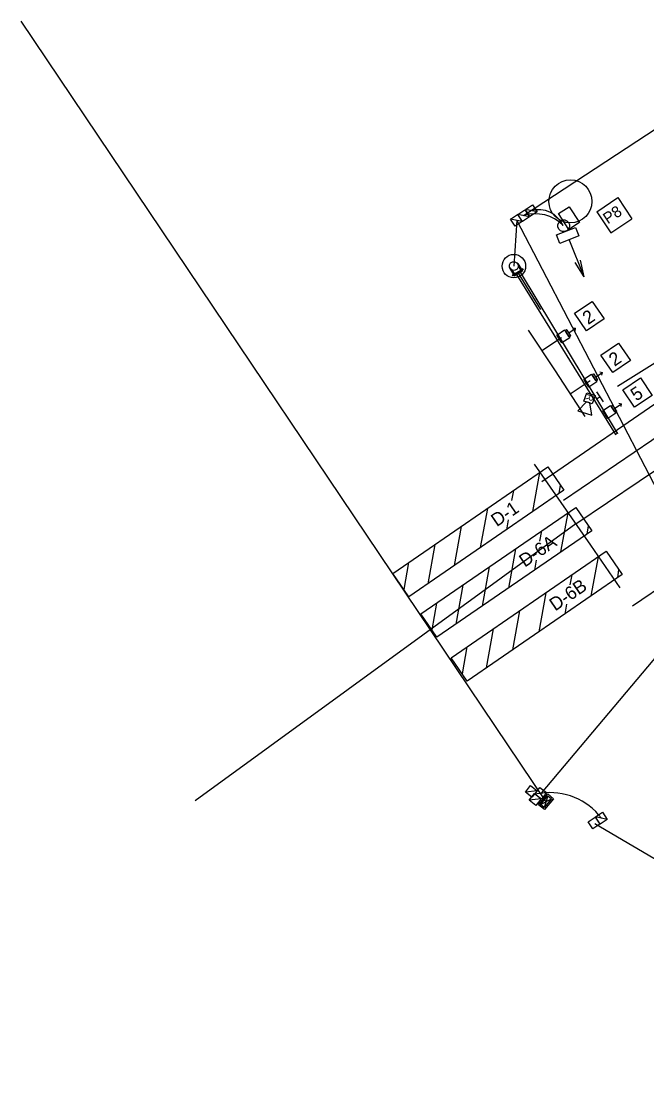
# Model space of a CAD drawing. Extents: x 509004 to 509991, y 882089 to 882397.
# Drawn here: x 509003.6 to 509136.6, y 882120.7 to 882344.8 of the extents above; entities that cross this region are included whole.
import ezdxf

# ---------------------------------------------------------------- set-up
doc = ezdxf.new("R2010")
doc.units = 0
for name, color, linetype in [('CLConst_dp', 7, 'Continuous'), ('ConstLines', 7, 'Continuous'), ('Default', 7, 'Continuous'), ('TextAlgnCardinalPnt', 7, 'Continuous'), ('TextAlgnCurveData', 7, 'Continuous'), ('TextAlgnStation100', 7, 'Continuous'), ('TextAlgnStation1000', 7, 'Continuous'), ('TextAlgnStation500', 7, 'Continuous'), ('TextAlgnStation5000', 7, 'Continuous'), ('TextAlgnTangent', 7, 'Continuous'), ('TextAlgnTicks1000', 7, 'Continuous'), ('TextAlgnTicks500', 7, 'Continuous'), ('TextAlgnTicks5000', 7, 'Continuous')]:
    doc.layers.add(name, color=color, linetype=linetype)

msp = doc.modelspace()

# ---------------------------------------------------------------- linework, layer by layer
at = {"layer": 'CLConst_dp'}
for p, q in [((509107.51, 882292.21), (509107.56, 882292.24)), ((509107.51, 882292.21), (509108.28, 882290.94)), ((509107.56, 882292.24), (509108.33, 882290.98)), ((509107.94, 882291.89), (509108.5, 882290.98)), ((509110.35, 882292), (509108.07, 882290.61)), ((509108.32, 882290.77), (509110.1, 882291.85)), ((509109.82, 882291.79), (509108.5, 882290.98)), ((509109.18, 882293.23), (509109.13, 882293.2)), ((509109.13, 882293.2), (509109.9, 882291.93)), ((509109.18, 882293.23), (509109.96, 882291.97)), ((509109.27, 882292.7), (509109.82, 882291.79)), ((509110.26, 882292.15), (509109.78, 882291.86)), ((509110.1, 882291.85), (509110.18, 882291.71)), ((509110.26, 882292.15), (509110.35, 882292)), ((509108.46, 882291.05), (509107.98, 882290.76)), ((509107.98, 882290.76), (509108.07, 882290.61)), ((509108.32, 882290.77), (509108.41, 882290.62)), ((509108.41, 882290.62), (509110.18, 882291.71)), ((509108.9, 882290.93), (509129.95, 882256.91)), ((509109.69, 882291.41), (509130.34, 882257.15)), ((509130.44, 882257.21), (509129.84, 882256.85))]:
    msp.add_line(p, q, dxfattribs=at)
msp.add_lwpolyline([(509109.04, 882292.06), (509108.62, 882291.81), (509108.12, 882291.79), (509107.69, 882292.03), (509107.43, 882292.45), (509107.42, 882292.94), (509107.66, 882293.37), (509108.08, 882293.63), (509108.57, 882293.64), (509109, 882293.41), (509109.26, 882292.99), (509109.27, 882292.49)], close=True, dxfattribs=at)
msp.add_circle((509108.35, 882292.7), 2.5, dxfattribs=at)
at = {"layer": 'ConstLines'}
for p, q in [((509115.19, 882178.82), (509003.6, 882344.8)), ((509238.53, 882335.06), (509130.35, 882267.1)), ((509114.28, 882246.89), (509215.66, 882316.8)), ((509121.5, 882237.9), (509226.04, 882308.24)), ((509114.27, 882274.75), (509118.51, 882277.53)), ((509120.29, 882265.57), (509124.54, 882268.35)), ((509118.93, 882242.94), (509141.44, 882258.22)), ((509121.5, 882237.9), (509040.64, 882179.01))]:
    msp.add_line(p, q, dxfattribs=at)
for points in [[(509111.42, 882279.1), (509117.13, 882270.4), (509123.46, 882260.74)], [(509112.68, 882250.62), (509118.37, 882242.43), (509124.63, 882233.36), (509130.88, 882224.29)]]:
    msp.add_lwpolyline(points, dxfattribs=at)
msp.add_circle((509120.38, 882306.46), 4.58, dxfattribs=at)
at = {"layer": 'Default'}
msp.add_line((509133.54, 882220.5), (509164.96, 882241.77), dxfattribs=at)
at = {"layer": 'TextAlgnCardinalPnt'}
for p, q in [((509150.12, 882223.33), (509108.95, 882302.45)), ((509114.21, 882180.66), (509150.12, 882223.33))]:
    msp.add_line(p, q, dxfattribs=at)
at = {"layer": 'TextAlgnCurveData'}
for p, q in [((509110.42, 882303.44), (509138.84, 882322.08)), ((509108.95, 882302.45), (509108.35, 882292.72))]:
    msp.add_line(p, q, dxfattribs=at)
for centre, radius, start, end in [((509112.91, 882295.6), 8.23, 43.9393, 107.6121), ((509113.56, 882298.91), 5.79, 24.4306, 105.2087), ((509116.08, 882167.13), 13.62, 36.983, 98.5568)]:
    msp.add_arc(centre, radius, start, end, dxfattribs=at)
at = {"layer": 'TextAlgnStation100'}
for p, q in [((509110.8, 882304.76), (509112.3, 882305.74)), ((509112.3, 882305.74), (509113.28, 882304.24)), ((509107.64, 882302.69), (509109.14, 882303.67)), ((509109.14, 882303.67), (509110.12, 882302.17)), ((509109.18, 882303.7), (509110.68, 882304.68)), ((509110.16, 882302.2), (509109.18, 882303.7)), ((509111.66, 882303.18), (509109.18, 882303.7)), ((509111.66, 882303.18), (509110.16, 882302.2)), ((509110.68, 882304.68), (509111.66, 882303.18)), ((509111.78, 882303.26), (509110.8, 882304.76)), ((509113.28, 882304.24), (509110.8, 882304.76)), ((509113.28, 882304.24), (509111.78, 882303.26)), ((509108.62, 882301.19), (509107.64, 882302.69)), ((509110.12, 882302.17), (509107.64, 882302.69)), ((509110.12, 882302.17), (509108.62, 882301.19)), ((509110.79, 882180.86), (509111.89, 882182.27)), ((509111.89, 882182.27), (509113.3, 882181.17)), ((509113.3, 882181.17), (509110.79, 882180.86)), ((509112.2, 882179.76), (509110.79, 882180.86)), ((509111.61, 882179.13), (509112.71, 882180.54)), ((509113.3, 882181.17), (509112.2, 882179.76)), ((509112.71, 882180.54), (509114.12, 882179.43)), ((509112.8, 882180.45), (509113.9, 882181.86)), ((509115.31, 882180.75), (509112.8, 882180.45)), ((509114.21, 882179.34), (509112.8, 882180.45)), ((509113.9, 882181.86), (509115.31, 882180.75)), ((509115.31, 882180.75), (509114.21, 882179.34)), ((509114.12, 882179.43), (509111.61, 882179.13)), ((509113.02, 882178.02), (509111.61, 882179.13)), ((509114.12, 882179.43), (509113.02, 882178.02)), ((509125.72, 882175.58), (509127.22, 882176.57)), ((509126.71, 882174.08), (509125.72, 882175.58)), ((509128.2, 882175.07), (509125.72, 882175.58)), ((509127.22, 882176.57), (509128.2, 882175.07)), ((509128.2, 882175.07), (509126.71, 882174.08))]:
    msp.add_line(p, q, dxfattribs=at)
msp.add_lwpolyline([(509124.12, 882174.53), (509125.62, 882175.52), (509126.61, 882174.02), (509125.11, 882173.04)], close=True, dxfattribs=at)
at = {"layer": 'TextAlgnStation1000'}
for p, q in [((509120.05, 882277.76), (509119.33, 882278.85)), ((509120.4, 882277.99), (509119.68, 882279.08)), ((509120.4, 882277.99), (509119.68, 882279.08)), ((509120.04, 882278.54), (509121.48, 882279.48)), ((509120.89, 882279.6), (509121.48, 882279.48)), ((509121.35, 882278.89), (509121.48, 882279.48)), ((509125.77, 882268.38), (509125.05, 882269.47)), ((509126.13, 882268.61), (509125.4, 882269.71)), ((509126.13, 882268.61), (509125.4, 882269.71)), ((509125.76, 882269.16), (509127.2, 882270.1)), ((509126.61, 882270.22), (509127.2, 882270.1)), ((509127.08, 882269.51), (509127.2, 882270.1)), ((509129.83, 882261.7), (509129.11, 882262.8)), ((509130.18, 882261.93), (509129.46, 882263.03)), ((509130.18, 882261.93), (509129.46, 882263.03)), ((509129.82, 882262.48), (509131.26, 882263.42)), ((509130.67, 882263.54), (509131.26, 882263.42)), ((509131.14, 882262.83), (509131.26, 882263.42))]:
    msp.add_line(p, q, dxfattribs=at)
for points in [[(509127.52, 882281.48), (509123.77, 882278.96), (509121.27, 882282.68), (509125.02, 882285.2)], [(509119.14, 882279.14), (509120.24, 882277.47), (509118.57, 882276.37), (509117.47, 882278.04)], [(509133.12, 882272.6), (509129.37, 882270.08), (509126.87, 882273.8), (509130.62, 882276.32)], [(509124.86, 882269.76), (509125.96, 882268.09), (509124.29, 882266.99), (509123.19, 882268.66)], [(509137.74, 882265.2), (509133.99, 882262.68), (509131.49, 882266.4), (509135.24, 882268.92)], [(509128.92, 882263.08), (509130.02, 882261.41), (509128.35, 882260.31), (509127.25, 882261.99)]]:
    msp.add_lwpolyline(points, close=True, dxfattribs=at)
for points in [[(509119.33, 882278.85), (509120.05, 882277.76)], [(509125.05, 882269.47), (509125.77, 882268.38)], [(509129.11, 882262.8), (509129.83, 882261.7)]]:
    msp.add_lwpolyline(points, dxfattribs=at)
for centre, radius, start, end in [((509117.33, 882280.17), 2.4, 326.5349, 332.6381), ((509117.33, 882280.17), 2.4, 326.5349, 332.6381), ((509119.58, 882279.01), 0.129, 33.3183, 152.6381), ((509119.58, 882279.01), 0.129, 33.3183, 152.6381), ((509120.47, 882275.4), 2.4, 93.9985, 100.1017), ((509120.47, 882275.4), 2.4, 93.9985, 100.1017), ((509120.3, 882277.92), 0.129, 273.9985, 33.3183), ((509120.3, 882277.92), 0.129, 273.9985, 33.3183), ((509123.05, 882270.8), 2.4, 326.5349, 332.6381), ((509123.05, 882270.8), 2.4, 326.5349, 332.6381), ((509125.3, 882269.64), 0.129, 33.3183, 152.6381), ((509125.3, 882269.64), 0.129, 33.3183, 152.6381), ((509126.19, 882266.02), 2.4, 93.9985, 100.1017), ((509126.19, 882266.02), 2.4, 93.9985, 100.1017), ((509126.02, 882268.54), 0.129, 273.9985, 33.3183), ((509126.02, 882268.54), 0.129, 273.9985, 33.3183), ((509127.11, 882264.12), 2.4, 326.5349, 332.6381), ((509127.11, 882264.12), 2.4, 326.5349, 332.6381), ((509129.36, 882262.96), 0.129, 33.3183, 152.6381), ((509129.36, 882262.96), 0.129, 33.3183, 152.6381), ((509130.25, 882259.34), 2.4, 93.9985, 100.1017), ((509130.25, 882259.34), 2.4, 93.9985, 100.1017), ((509130.08, 882261.86), 0.129, 273.9985, 33.3183), ((509130.08, 882261.86), 0.129, 273.9985, 33.3183)]:
    msp.add_arc(centre, radius, start, end, dxfattribs=at)
at = {"layer": 'TextAlgnStation500'}
for p, q in [((509125.96, 882304.24), (509130.44, 882307.26)), ((509130.44, 882307.26), (509133.46, 882302.78)), ((509125.96, 882304.24), (509128.98, 882299.77)), ((509128.98, 882299.77), (509133.46, 882302.78)), ((509123.27, 882290.45), (509120.12, 882298.35)), ((509123.27, 882290.45), (509121.38, 882293.5)), ((509123.27, 882290.45), (509122.54, 882293.96))]:
    msp.add_line(p, q, dxfattribs=at)
at = {"layer": 'TextAlgnStation5000'}
for p, q in [((509113.61, 882178.19), (509115.54, 882180.49)), ((509114.04, 882178.23), (509115.58, 882180.07)), ((509115.58, 882180.07), (509114.8, 882177.58)), ((509115.54, 882180.49), (509116.77, 882179.46)), ((509115.58, 882180.07), (509116.34, 882179.42)), ((509114.84, 882177.16), (509113.61, 882178.19)), ((509114.04, 882178.23), (509116.34, 882179.42)), ((509114.8, 882177.58), (509114.04, 882178.23)), ((509116.34, 882179.42), (509114.8, 882177.58)), ((509116.77, 882179.46), (509114.84, 882177.16))]:
    msp.add_line(p, q, dxfattribs=at)
at = {"layer": 'TextAlgnTicks1000'}
for p, q in [((509124.5, 882263.6), (509123.76, 882263.83)), ((509082.6, 882227.34), (509115.57, 882250)), ((509115.57, 882250), (509118.97, 882245.05)), ((509112.39, 882240.53), (509113.9, 882248.85)), ((509118.97, 882245.05), (509086, 882222.4)), ((509107.91, 882242.84), (509108.31, 882245.01)), ((509118.01, 882244.39), (509118.29, 882246.04)), ((509088.56, 882218.74), (509121.53, 882241.39)), ((509102.72, 882241.17), (509101.22, 882232.86)), ((509118.35, 882231.92), (509119.86, 882240.24)), ((509121.53, 882241.39), (509124.93, 882236.45)), ((509107.16, 882238.77), (509106.76, 882236.66)), ((509124.93, 882236.45), (509091.96, 882213.79)), ((509097.14, 882237.33), (509095.64, 882229.02)), ((509113.87, 882234.24), (509114.27, 882236.4)), ((509123.96, 882235.78), (509124.25, 882237.44)), ((509091.55, 882233.49), (509090.05, 882225.18)), ((509095.02, 882209.42), (509127.98, 882232.07)), ((509108.68, 882232.56), (509107.18, 882224.25)), ((509127.98, 882232.07), (509131.38, 882227.13)), ((509085.96, 882229.65), (509084.93, 882223.95)), ((509113.12, 882230.17), (509112.71, 882228.05)), ((509124.8, 882222.6), (509126.31, 882230.92)), ((509086, 882222.4), (509082.6, 882227.34)), ((509131.38, 882227.13), (509098.41, 882204.47)), ((509103.1, 882228.73), (509101.6, 882220.42)), ((509120.32, 882224.92), (509120.72, 882227.08)), ((509130.42, 882226.46), (509130.7, 882228.12)), ((509097.51, 882224.89), (509096.01, 882216.58)), ((509115.14, 882223.24), (509113.64, 882214.93)), ((509091.92, 882221.05), (509090.89, 882215.35)), ((509119.57, 882220.85), (509119.17, 882218.73)), ((509091.96, 882213.79), (509088.56, 882218.74)), ((509109.55, 882219.41), (509108.05, 882211.1)), ((509103.96, 882215.57), (509102.46, 882207.26)), ((509098.38, 882211.73), (509097.35, 882206.03)), ((509098.41, 882204.47), (509095.02, 882209.42)), ((509125.57, 882174.22), (509216.27, 882120.73))]:
    msp.add_line(p, q, dxfattribs=at)
msp.add_lwpolyline([(509123.25, 882264), (509123.83, 882265.79), (509125.6, 882265.22), (509125.02, 882263.43)], close=True, dxfattribs=at)
msp.add_lwpolyline([(509123.76, 882263.83), (509121.93, 882261.95), (509124.89, 882261), (509124.5, 882263.6)], dxfattribs=at)
at = {"layer": 'TextAlgnTicks500'}
for p, q in [((509117.39, 882299.32), (509121.42, 882300.93)), ((509121.42, 882300.93), (509122.13, 882299.15)), ((509118.1, 882297.54), (509117.39, 882299.32)), ((509122.13, 882299.15), (509118.1, 882297.54))]:
    msp.add_line(p, q, dxfattribs=at)
msp.add_lwpolyline([(509120.05, 882300.52), (509117.86, 882303.87), (509120.09, 882305.33), (509122.28, 882301.98)], close=True, dxfattribs=at)
msp.add_ellipse((509118.94, 882301.28), major_axis=(1.03, 0.71), ratio=0.999996, dxfattribs=at)
at = {"layer": 'TextAlgnTicks5000'}
for p, q in [((509109.29, 882291.17), (509113.99, 882283.48)), ((509126.69, 882264.91), (509125.84, 882264.35)), ((509127.37, 882263.87), (509126, 882265.96))]:
    msp.add_line(p, q, dxfattribs=at)

# ---------------------------------------------------------------- texts
at = {"layer": 'TextAlgnStation1000'}
for s, p in [('2', (509124.14, 882280.16)), ('2', (509129.74, 882271.28)), ('5', (509134.36, 882263.88))]:
    msp.add_text(s, height=2.8, rotation=33.9138, dxfattribs=at).set_placement(p)
at = {"layer": 'TextAlgnStation500'}
msp.add_text('P8', height=2.399, rotation=33.9138, dxfattribs=at).set_placement((509128.32, 882301.56))
at = {"layer": 'TextAlgnTangent'}
for s, p in [('D-1', (509104.72, 882237.18)), ('D-6A', (509110.68, 882228.57)), ('D-6B', (509117.13, 882219.25))]:
    msp.add_text(s, height=2.8, rotation=34.495, dxfattribs=at).set_placement(p)
at = {"layer": 'TextAlgnTicks1000'}
msp.add_text('R', height=1.49, rotation=252.0898, dxfattribs=at).set_placement((509123.98, 882265.65))

doc.saveas('drawing.dxf')
